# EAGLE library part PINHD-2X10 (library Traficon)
PIN HEADER
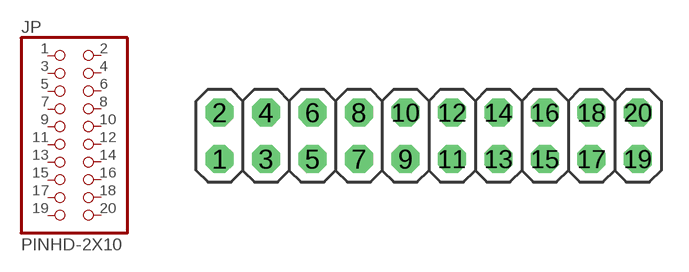
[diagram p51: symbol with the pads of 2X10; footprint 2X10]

Designator prefix JP

## PINHD-2X10  [2X10]
1  1  pas
2  2  pas
3  3  pas
4  4  pas
5  5  pas
6  6  pas
7  7  pas
8  8  pas
9  9  pas
10  10  pas
11  11  pas
12  12  pas
13  13  pas
14  14  pas
15  15  pas
16  16  pas
17  17  pas
18  18  pas
19  19  pas
20  20  pas

## Footprint 2X10 (pad centres in mm)
PIN HEADER
drill 1.016 octagon: 1 0,-2.54; 2 0,0; 3 2.54,-2.54; 4 2.54,0; 5 5.08,-2.54; 6 5.08,0; 7 7.62,-2.54; 8 7.62,0; 9 10.16,-2.54; 10 10.16,0; 11 12.7,-2.54; 12 12.7,0; 13 15.24,-2.54; 14 15.24,0; 15 17.78,-2.54; 16 17.78,0; 17 20.32,-2.54; 18 20.32,0; 19 22.86,-2.54; 20 22.86,0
